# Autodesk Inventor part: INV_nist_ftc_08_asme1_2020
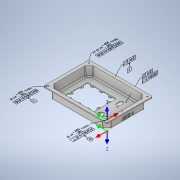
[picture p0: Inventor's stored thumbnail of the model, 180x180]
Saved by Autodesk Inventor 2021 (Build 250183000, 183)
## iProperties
Created: 2016-11
Part Number: INV_nist_ftc_08_asme1_2020
Material: Generic
Document SubType Name: Modeling
Designer: t_liuje
Density: 1 g/cm^3
Appearance: Default
Author: t_liuje
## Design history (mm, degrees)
node "Parallel Axes Pattern 1"
  node "Simple Hole 35"
  node "Simple Hole 36"
  node "Hole Note 13" dims "d5" = 291.1602, "d6" = 204.0382, "d141" = 22.86, "d142" = 22.86 (derived), "d143" = 22.86 (derived), "d144" = 22.86 (derived), "d145" = 22.86 (derived), "d146" = 22.86 (derived), "d147" = 22.86 (derived), "d148" = 22.86 (derived)
  node "Feature Control Frame 72"
node "Parallel Axes Pattern 2"
  node "Simple Hole 25"
  node "Simple Hole 26"
  node "Simple Hole 27"
  node "Simple Hole 28"
  node "Simple Hole 29"
  node "Simple Hole 30"
  node "Simple Hole 31"
  node "Simple Hole 32"
  node "Diameter Dimension 19" dims "d5" = 291.1602, "d6" = 204.0382, "d141" = 22.86, "d142" = 22.86 (derived), "d143" = 22.86 (derived), "d144" = 22.86 (derived), "d145" = 22.86 (derived), "d146" = 22.86 (derived), "d147" = 22.86 (derived), "d148" = 22.86 (derived), "d688" = 5.4102 (derived)
  node "Feature Control Frame 56"
node "Parallel Axes Pattern 3" dims "d231" = 9.14552 (derived), "d232" = 7.51656 (derived), "d233" = 0.508 (derived), "d234" = 0 (derived), "d235" = 0 (derived), "d236" = 1.524 (derived), "d237" = 0 (derived), "d238" = 0 (derived), "d247" = 27.94 (derived), "d315" = 5.33671 (derived), "d316" = 3.69003 (derived), "d347" = 15.24 (derived), "d348" = 0 (derived), "d349" = 0 (derived), "d505" = 0 (derived), "d506" = 0 (derived), "d541" = 3.50258 (derived), "d542" = 1.1618 (derived), "d543" = 1.524 (derived), "d544" = 0 (derived), "d545" = 0 (derived), "d598" = 0.2885 (derived), "d599" = 8.19502 (derived), "d600" = 0.381 (derived)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
  node "Simple Hole 33"
  node "Simple Hole 34"
  node "Diameter Dimension 20" dims "d5" = 291.1602, "d6" = 204.0382, "d141" = 22.86, "d142" = 22.86 (derived), "d143" = 22.86 (derived), "d144" = 22.86 (derived), "d145" = 22.86 (derived), "d146" = 22.86 (derived), "d147" = 22.86 (derived), "d148" = 22.86 (derived), "d717" = 6.35 (derived)
  node "Feature Control Frame 59"
  node "Datum Identifier 33" dims "d6" = 204.0382, "d231" = 9.14552 (derived), "d232" = 7.51656 (derived), "d233" = 0.508 (derived), "d234" = 0 (derived), "d235" = 0 (derived), "d236" = 1.524 (derived), "d237" = 0 (derived), "d238" = 0 (derived), "d247" = 27.94 (derived), "d315" = 5.33671 (derived), "d316" = 3.69003 (derived), "d347" = 15.24 (derived), "d348" = 0 (derived), "d349" = 0 (derived), "d505" = 0 (derived), "d506" = 0 (derived), "d541" = 3.50258 (derived), "d542" = 1.1618 (derived), "d543" = 1.524 (derived), "d544" = 0 (derived), "d545" = 0 (derived), "d598" = 0.2885 (derived), "d599" = 8.19502 (derived)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
node "Datum Reference Frame 16"
node "Datum Reference Frame 17"
node "Datum Reference Frame 18"
node "Datum Reference Frame 19"
node "Planar Surface 34"
  node "Feature Control Frame 43"
node "Planar Surface 35"
  node "Feature Control Frame 53"
  node "Leader Text 16"
node "Extruded Group 5"
  node "Cylindrical Surface 19"
  node "Planar Surface 40"
  node "Planar Surface 41"
  node "Planar Surface 42"
  node "Planar Surface 43"
  node "Planar Surface 44"
  node "Cylindrical Surface 20"
  node "Cylindrical Surface 21"
  node "Planar Surface 45"
  node "Planar Surface 46"
  node "Feature Control Frame 67"
node "Extruded Group 6"
  node "Planar Surface 47"
  node "Cylindrical Surface 24"
  node "Cylindrical Surface 25"
  node "Cylindrical Surface 26"
  node "Planar Surface 48"
  node "Cylindrical Surface 27"
  node "Planar Surface 49"
  node "Cylindrical Surface 28"
  node "Cylindrical Surface 29"
  node "Cylindrical Surface 30"
  node "Planar Surface 50"
  node "Cylindrical Surface 31"
  node "Cylindrical Surface 32"
  node "Cylindrical Surface 33"
  node "Planar Surface 51"
  node "Cylindrical Surface 34"
  node "Planar Surface 52"
  node "Cylindrical Surface 35"
  node "Cylindrical Surface 36"
  node "Cylindrical Surface 37"
  node "Planar Surface 53"
  node "Cylindrical Surface 38"
  node "Cylindrical Surface 39"
  node "Cylindrical Surface 40"
  node "Planar Surface 54"
  node "Cylindrical Surface 41"
  node "Cylindrical Surface 42"
  node "Cylindrical Surface 43"
  node "Planar Surface 55"
  node "Cylindrical Surface 44"
  node "Planar Surface 56"
  node "Cylindrical Surface 45"
  node "Cylindrical Surface 46"
  node "Cylindrical Surface 47"
  node "Planar Surface 57"
  node "Cylindrical Surface 48"
  node "Cylindrical Surface 49"
  node "Cylindrical Surface 50"
  node "Planar Surface 58"
  node "Cylindrical Surface 51"
  node "Planar Surface 59"
  node "Cylindrical Surface 52"
  node "Cylindrical Surface 53"
  node "Cylindrical Surface 54"
  node "Planar Surface 60"
  node "Cylindrical Surface 55"
  node "Cylindrical Surface 56"
  node "Cylindrical Surface 57"
  node "Feature Control Frame 73"
node "Extruded Group 7"
  node "Planar Surface 61"
  node "Cylindrical Surface 58"
  node "Planar Surface 62"
  node "Cylindrical Surface 59"
  node "Planar Surface 63"
  node "Planar Surface 64"
  node "Cylindrical Surface 60"
  node "Cylindrical Surface 61"
  node "Feature Control Frame 74"
body "Solid1"
node "Blocks"
node "Annotations"
node "Tolerance Features"
sketch "Sketch1"
  geometry: L1 (155.804, -111.354)-(-155.804, -111.354); L2 (-155.804, -111.354)-(-155.804, 111.354); L3 (-155.804, 111.354)-(155.804, 111.354); L4 (155.804, 111.354)-(155.804, -111.354); L5 (0, -145.063)-(0, 157.515); L6 (136.916, 0)-(-164.263, 0); 1 further point
  constraints: 12 end point, 2 horizontal, 2 parallel, 2 point on line, 1 perpendicular, 1 vertical, 2 other
  dimensions: "d0" = 311.6072 distance of L2.end L3.end; "d1" = 222.7072 distance of L1.end L2.end
extrude "Extrusion1" new body sketch "Sketch1" distance "d2" = 10.16; taper "d3" = 0 deg
feature "FaceDraft1" dims angle "d4" = -2.5 deg
sketch "Sketch2"
  geometry: L1 (0, -151.447)-(0, 170.59); L2 (373.907, 0)-(-297.418, 0); L3 (-122.72, -102.019)-(122.72, -102.019); L4 (145.58, -79.159)-(145.58, 79.159); L5 (122.72, 102.019)-(-122.72, 102.019); L6 (-145.58, 79.159)-(-145.58, -79.159); L7 (-122.72, 102.019)-(-145.58, 79.159); L8 (-145.58, -79.159)-(-122.72, -102.019); L9 (122.72, -102.019)-(145.58, -79.159); L10 (145.58, 79.159)-(122.72, 102.019); 5 further points
  constraints: 20 end point, 10 point on line, 2 horizontal, 2 parallel, 1 perpendicular, 1 vertical, 2 other
  dimensions: "d5" = 291.1602 distance of point (145.58, 102.019) point (-145.58, 102.019); "d6" = 204.0382 distance of point (145.58, -102.019) point (145.58, 102.019); "d141" = 22.86 distance of L5.end point (-145.58, 102.019); "d142" = 22.86 distance of L6.start point (-145.58, 102.019) (derived); "d143" = 22.86 distance of L6.end point (-145.58, -102.019) (derived); "d144" = 22.86 distance of L3.start point (-145.58, -102.019) (derived); "d145" = 22.86 distance of L3.end point (145.58, -102.019) (derived); "d146" = 22.86 distance of L4.start point (145.58, -102.019) (derived); "d147" = 22.86 distance of L4.end point (145.58, 102.019) (derived); "d148" = 22.86 distance of L5.start point (145.58, 102.019) (derived)
extrude "Extrusion2" join sketch "Sketch2" distance "d7" = 38.1; taper "d8" = 0 deg
feature "FaceDraft2" dims angle "d9" = 2.5 deg
workplane "Work Plane1"
sketch "Sketch3"
  geometry: L1 (0, -206.645)-(0, 206.645); L2 (-285.873, 0)-(333.246, 0); L3 (-119.456, -94.158)-(119.456, -94.158); L4 (137.719, -75.895)-(137.719, 75.895); L5 (119.456, 94.158)-(-119.456, 94.158); L6 (-137.719, 75.895)-(-137.719, -75.895); L7 (-119.456, -94.158)-(-137.719, -75.895); L8 (-137.719, 75.895)-(-119.456, 94.158); L9 (119.456, 94.158)-(137.719, 75.895); L10 (119.456, -94.158)-(137.719, -75.895); 6 further points
  constraints: 20 end point, 9 point on line, 2 parallel, 2 perpendicular, 1 coincident, 1 horizontal, 1 midpoint, 1 vertical, 2 other
  dimensions: "d11" = 275.4376 distance of point (-137.719, 94.158) point (137.719, 94.158); "d12" = 188.3156 distance of point (137.719, 94.158) point (137.719, -94.158); "d16" = 18.2626 distance of L3.start point (-137.719, -94.158); "d17" = 18.2626 distance of L6.end point (-137.719, -94.158) (= d16); "d18" = 18.2626 distance of L6.start point (-137.719, 94.158) (= d16); "d19" = 18.2626 distance of L5.end point (-137.719, 94.158) (= d18); "d20" = 18.2626 distance of L5.start point (137.719, 94.158) (= d16); "d21" = 18.2626 distance of L4.end point (137.719, 94.158) (= d20); "d22" = 18.2626 distance of L3.end point (137.719, -94.158) (= d16); "d23" = 18.2626 distance of L4.start point (137.719, -94.158) (= d22)
extrude "Extrusion3" cut sketch "Sketch3" stored distance "d13" = 38.1; taper "d14" = 0 deg
feature "FaceDraft3" dims angle "d15" = 2.5 deg
fillet "Fillet1" dims "d24" = 3.048
fillet "Fillet2" dims "d25" = 6.096
sketch "Sketch4"
  geometry: L1 (-127.635, 79.375)-(-121.285, 79.375); L2 (-118.11, 76.2)-(-118.11, -76.2); L3 (-121.285, -79.375)-(-127.635, -79.375); L4 (-130.81, -76.2)-(-130.81, 76.2); L5 (-237.716, 0)-(182.507, 0); L6 (-155.804, -105.263)-(-155.804, 105.263) reference; A1 r 3.175 centre (-127.635, 76.2) between (-127.635, 79.375) and (-130.81, 76.2); A2 r 3.175 centre (-121.285, 76.2) between (-118.11, 76.2) and (-121.285, 79.375); A3 r 3.175 centre (-127.635, -76.2) between (-130.81, -76.2) and (-127.635, -79.375); A4 r 3.175 centre (-121.285, -76.2) between (-121.285, -79.375) and (-118.11, -76.2); 4 further points
  constraints: 10 end point, 8 point on circle, 8 tangent, 7 point on line, 4 centre point, 3 equal radius, 2 horizontal, 2 parallel, 1 perpendicular, 1 other
  dimensions: "d26" = 12.7 distance of point (-118.11, -79.375) point (-130.81, -79.375); "d27" = 158.75 distance of point (-118.11, 79.375) point (-118.11, -79.375); "d28" = 24.9936 distance between parallel lines of L6 L4; "d29" = 3.175 radius of A1
extrude "Extrusion4" cut sketch "Sketch4" distance "d30" = 1.27; taper "d31" = 0 deg
fillet "Fillet3" dims "d32" = 0.762
sketch "Sketch5"
  geometry: L1 (-252.407, 0)-(214.454, 0); L2 (0, 149.282)-(0, -167.26); L3 (-155.804, -105.263)-(-155.804, 105.263) reference; L4 (-90.016, -57.15)-(-107.95, -57.15); L5 (-45.566, -57.15)-(-75.084, -57.15); L6 (31.75, -57.15)-(13.816, -57.15); L7 (0, -57.15)-(-30.634, -57.15); L8 (31.75, -32.866)-(31.75, -57.15); L9 (31.75, 57.15)-(31.75, 32.866); L10 (31.75, 17.934)-(31.75, -17.934); L11 (13.816, 57.15)-(31.75, 57.15); L12 (-30.634, 57.15)-(0, 57.15); L13 (-107.95, 57.15)-(-90.016, 57.15); L14 (-75.084, 57.15)-(-45.566, 57.15); L15 (-107.95, 32.866)-(-107.95, 57.15); L16 (-107.95, -57.15)-(-107.95, -32.866); L17 (-107.95, -17.934)-(-107.95, 17.934); L18 (155.804, 105.263)-(155.804, -105.263) reference; L19 (-149.713, 111.354)-(149.713, 111.354) reference; L20 (46.99, 52.705)-(52.07, 52.705); L21 (52.07, 40.005)-(46.99, 40.005); L22 (46.99, 40.005)-(46.99, 52.705); L23 (52.07, 38.1)-(52.07, 40.005); L24 (52.07, 52.705)-(52.07, 54.61); L25 (67.31, 54.61)-(67.31, 51.435); L26 (67.31, 41.275)-(67.31, 38.1); L27 (96.85, -35.56)-(121.59, -35.56); L28 (123.19, -37.16)-(123.19, -61.9); L29 (121.59, -63.5)-(96.85, -63.5); L30 (95.25, -61.9)-(95.25, -37.16); L31 (149.713, -111.354)-(-149.713, -111.354) reference; L32 (67.31, -38.1)-(67.31, -41.275); L33 (67.31, -51.435)-(67.31, -54.61); L34 (52.07, -38.1)-(52.07, -54.61); C1 r 2.705 at (-82.55, 55.626); C2 r 2.705 at (-38.1, 55.626); C3 r 2.705 at (6.35, 55.626); C4 r 2.705 at (-82.55, -55.626); C5 r 2.705 at (-38.1, -55.626); C6 r 2.705 at (6.35, -55.626); C7 r 2.705 at (-106.426, 25.4); C8 r 2.705 at (-106.426, -25.4); C9 r 2.705 at (30.226, 25.4); C10 r 2.705 at (30.226, -25.4); C11 r 3.073 at (69.85, 67.31); C12 r 2.896 at (69.85, 25.4); C13 r 3.175 at (109.22, -20.955); C14 r 3.175 at (109.22, -78.105); C15 r 2.896 at (69.85, -67.31); C16 r 3.073 at (69.85, -25.4); A1 r 7.62 centre (-82.55, 55.626) between (-90.016, 57.15) and (-75.084, 57.15); A2 r 7.62 centre (-38.1, 55.626) between (-45.566, 57.15) and (-30.634, 57.15); A3 r 7.62 centre (6.35, 55.626) between (-1.116, 57.15) and (13.816, 57.15); A4 r 7.62 centre (-82.55, -55.626) between (-75.084, -57.15) and (-90.016, -57.15); A5 r 7.62 centre (-38.1, -55.626) between (-30.634, -57.15) and (-45.566, -57.15); A6 r 7.62 centre (6.35, -55.626) between (13.816, -57.15) and (-1.116, -57.15); A7 r 7.62 centre (-106.426, 25.4) between (-107.95, 17.934) and (-107.95, 32.866); A8 r 7.62 centre (-106.426, -25.4) between (-107.95, -32.866) and (-107.95, -17.934); A9 r 7.62 centre (30.226, 25.4) between (31.75, 32.866) and (31.75, 17.934); A10 r 7.62 centre (30.226, -25.4) between (31.75, -17.934) and (31.75, -32.866); A11 r 15.291 centre (111.76, 63.5) between (96.787, 60.397) and (96.787, 66.603); A12 r 3.175 centre (97.46, 63.5) between (96.787, 66.603) and (96.787, 60.397); A13 r 5.08 centre (67.31, 46.355) between (67.31, 41.275) and (67.31, 51.435); A14 r 7.62 centre (59.69, 54.61) between (67.31, 54.61) and (52.07, 54.61); A15 r 7.62 centre (59.69, 38.1) between (52.07, 38.1) and (67.31, 38.1); A16 r 1.6 centre (96.85, -37.16) between (96.85, -35.56) and (95.25, -37.16); A17 r 1.6 centre (121.59, -37.16) between (123.19, -37.16) and (121.59, -35.56); A18 r 1.6 centre (96.85, -61.9) between (95.25, -61.9) and (96.85, -63.5); A19 r 1.6 centre (121.59, -61.9) between (121.59, -63.5) and (123.19, -61.9); A20 r 7.62 centre (59.69, -54.61) between (52.07, -54.61) and (67.31, -54.61); A21 r 7.62 centre (59.69, -38.1) between (67.31, -38.1) and (52.07, -38.1); A22 r 5.08 centre (67.31, -46.355) between (67.31, -51.435) and (67.31, -41.275); 4 further points
  constraints: 60 end point, 44 point on circle, 38 centre point, 32 parallel, 16 point on line, 16 tangent, 13 perpendicular, 10 coincident, 10 collinear, 7 horizontal, 4 equal radius, 4 vertical, 2 symmetric about line, 1 other
  dimensions: "d33" = 139.7 distance of L6.start L4.end; "d34" = 114.3 distance of L9.start L6.start; "d36" = 5.4102 diameter of C1; "d39" = 15.24 diameter of A1; "d40" = 5.4102 diameter of C2; "d41" = 15.24 diameter of A2; "d42" = 5.4102 diameter of C3; "d43" = 15.24 diameter of A3; "d48" = 44.45 distance of A2.centre A1.centre; "d49" = 44.45 distance of A2.centre A3.centre; "d50" = 5.4102 diameter of C4; "d51" = 15.24 diameter of A4; "d52" = 5.4102 diameter of C5; "d53" = 15.24 diameter of A5; "d54" = 5.4102 diameter of C6; "d55" = 15.24 diameter of A6; "d56" = 44.45 distance of A5.centre A4.centre; "d57" = 44.45 distance of A5.centre A6.centre; "d62" = 44.45 distance of C4.centre C5.centre (derived); "d63" = 44.45 distance of C6.centre C5.centre (derived); "d64" = 5.4102 diameter of C7; "d65" = 15.24 diameter of A7; "d66" = 5.4102 diameter of C8; "d67" = 15.24 diameter of A8; "d68" = 50.8 distance of A8.centre C7.centre; "d70" = 5.4102 diameter of C9; "d71" = 15.24 diameter of A9; "d72" = 5.4102 diameter of C10; "d73" = 15.24 diameter of A10; "d74" = 50.8 distance of A10.centre C9.centre; "d76" = 114.3 distance between parallel lines of L5 L14; "d77" = 139.7 distance between parallel lines of L10 L17; "d78" = 47.8536 distance between parallel lines of L3 L17; "d79" = 1.524 distance from line of L14 C1.centre; "d80" = 25.4 distance from line of L15 C1.centre; "d81" = 1.524 distance from line of L12 A2.centre; "d82" = 1.524 distance from line of L12 A3.centre; "d83" = 1.524 distance from line of L5 C4.centre; "d84" = 1.524 distance from line of A5.centre L5; "d85" = 25.4 distance from line of L16 A4.centre; "d86" = 1.524 distance from line of L6 A6.centre; "d87" = 1.524 distance from line of L8 A10.centre; "d88" = 1.524 distance from line of L16 C8.centre; "d89" = 30.5816 diameter of A11; "d90" = 44.0436 distance from line of L18 A11.centre; "d91" = 47.8536 distance from line of A11.centre L19; "d92" = 14.3002 distance of A12.centre A11.centre; "d93" = 47.8536 distance from line of A12.centre L19 (= d91); "d94" = 6.35 diameter of A12; "d95" = 10.16 diameter of A13; "d96" = 5.08 distance between parallel lines of L24 L22; "d97" = 5.08 distance of L21.start L21.end (= d96); "d98" = 12.7 distance of L21.end L20.start; "d99" = 15.24 distance between parallel lines of L24 L25; "d100" = 6.35 distance from line of A13.centre L20; "d101" = 56.7436 distance from line of L19 A14.centre; "d102" = 96.1136 distance from line of L18 A14.centre; "d103" = 16.51 distance of A15.centre A14.centre; "d104" = 1.905 distance from line of A14.centre L20; "d105" = 6.1468 diameter of C11; "d106" = 10.16 horizontal distance of C11.centre A14.centre; "d107" = 12.7 vertical distance of A14.centre C11.centre; "d108" = 10.16 horizontal distance of A15.centre C12.centre (derived); "d109" = 12.7 vertical distance of A15.centre C12.centre (derived)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
extrude "Extrusion5" cut sketch "Sketch5" stored distance "d130" = 25.4; taper "d131" = 0 deg
sketch "Sketch8"
  geometry: L1 (149.713, 111.354)-(-149.713, 111.354) reference; L2 (-155.804, 105.263)-(-155.804, -105.263) reference; 1 further point
  dimensions: "d132" = 12.9286 distance from line of L1 point (-142.875, 98.425); "d133" = 12.9286 distance from line of L2 point (-142.875, 98.425)
hole "Hole1" sketch "Sketch8" diameter "d134" = 6.0452; stored, may be unused: countersink angle "d138" = 82 deg, drill point angle "d140" = 118 deg; dims "d135" = 19.05, "d136" = 9.525, "d137" = 6.35, "d139" = 12.7
mirror "Mirror1"
mirror "Mirror2"
sketch "Sketch6"
  geometry: L1 (183.284, 13.514)-(183.095, 9.18) reference; L2 (183.095, 9.18)-(189.186, 8.914) reference; L3 (189.186, 8.914)-(189.375, 13.248) reference; L4 (-27.242, 13.514)-(183.284, 13.514) reference; 2 further points; 1 other entity
  constraints: 1 other
  dimensions: "d150" = 83.4136 dimension on L3.end; "d151" = 25.4 dimension on L4
extrude "Extrusion6" cut sketch "Sketch6" distance "d152" = 2.54; taper "d153" = 0 deg
fillet "Fillet4" dims "d196" = 3.175
sketch "Sketch7"
  geometry: L1 (70.782, -29.383)-(70.782, 0); L2 (170.85, 0)-(170.85, -29.383); L3 (170.85, -29.383)-(141.467, 0); L4 (160.074, -29.383)-(130.691, 0); L5 (149.297, -29.383)-(119.915, 0); L6 (138.521, -29.383)-(109.138, 0); L7 (127.745, -29.383)-(98.362, 0); L8 (116.969, -29.383)-(87.586, 0); L9 (106.192, -29.383)-(76.809, 0); L10 (95.416, -29.383)-(70.782, -4.749); L11 (84.64, -29.383)-(70.782, -15.525); L12 (73.863, -29.383)-(70.782, -26.301); L13 (170.85, -18.607)-(152.244, 0); L14 (170.85, -7.83)-(163.02, 0)
  constraints: 28 end point, 12 parallel, 5 point on line, 1 vertical, 24 other
split "Split1"
sketch "Block1"
  geometry: L1 (17.204, 76.896)-(6.4, 76.896); L2 (18.296, 92.7)-(18.296, 77.988); L3 (15.48, 83.59)-(15.48, 92.642); L4 (6.4, 108.85)-(6.4, 83.246); L5 (9.561, 108.85)-(6.4, 108.85); L6 (9.561, 102.44)-(9.561, 108.85); L7 (21.4, 102.44)-(9.561, 102.44); L8 (21.4, 99.338)-(21.4, 102.44); L9 (9.561, 99.338)-(21.4, 99.338); L10 (9.561, 83.648)-(9.561, 99.338); L11 (12.377, 93.16)-(12.377, 83.533); L12 (21.4, 77.959)-(21.4, 93.16); L13 (6.4, 73.763)-(17.204, 73.763); L14 (6.4, 76.896)-(6.4, 73.763); L15 (18.124, 67.902)-(7.023, 57.637); L16 (6.4, 68.62)-(17.808, 68.62); L17 (6.4, 71.752)-(6.4, 68.62); L18 (17.882, 71.752)-(6.4, 71.752); L19 (9.79, 56.022)-(20.08, 65.489); L20 (21.4, 55.085)-(10.156, 55.085); L21 (21.4, 51.982)-(21.4, 55.085); L22 (9.237, 51.982)-(21.4, 51.982); A1 r 1.093 centre (17.204, 77.988) between (17.204, 76.896) and (18.296, 77.988); A2 r 1.417 centre (16.891, 92.519) between (18.296, 92.7) and (15.48, 92.642); A3 r 4.547 centre (10.946, 83.246) between (6.4, 83.246) and (15.48, 83.59); A4 r 1.41 centre (10.966, 83.533) between (9.561, 83.648) and (12.377, 83.533); A5 r 4.568 centre (16.888, 92.441) between (21.4, 93.16) and (12.377, 93.16); A6 r 4.196 centre (17.204, 77.959) between (17.204, 73.763) and (21.4, 77.959); A7 r 3.261 centre (9.237, 55.243) between (7.023, 57.637) and (9.237, 51.982); A8 r 0.415 centre (17.842, 68.207) between (18.124, 67.902) and (17.808, 68.62); A9 r 3.517 centre (17.882, 68.235) between (20.08, 65.489) and (17.882, 71.752); A10 r 0.54 centre (10.156, 55.625) between (9.79, 56.022) and (10.156, 55.085); 1 further point
  constraints: 44 end point, 20 point on circle, 10 centre point
node "Projected Loop1"
node "Block1:1" dims "d150" = 83.4136, "d151" = 25.4
node "Planar Surface 1" dims "d231" = 9.14552 (derived), "d232" = 7.51656 (derived), "d233" = 0.508 (derived), "d234" = 0 (derived), "d235" = 0 (derived), "d236" = 1.524 (derived), "d237" = 0 (derived), "d238" = 0 (derived), "d247" = 27.94 (derived), "d315" = 5.33671 (derived), "d316" = 3.69003 (derived), "d347" = 15.24 (derived), "d348" = 0 (derived), "d349" = 0 (derived), "d505" = 0 (derived), "d506" = 0 (derived), "d541" = 3.50258 (derived), "d542" = 1.1618 (derived), "d543" = 1.524 (derived), "d544" = 0 (derived), "d545" = 0 (derived), "d598" = 0.2885 (derived), "d599" = 8.19502 (derived), "d600" = 0.381 (derived)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
node "Datum Reference Frame 1"
node "Simple Hole 1" dims "d231" = 9.14552 (derived), "d232" = 7.51656 (derived), "d233" = 0.508 (derived), "d234" = 0 (derived), "d235" = 0 (derived), "d236" = 1.524 (derived), "d237" = 0 (derived), "d238" = 0 (derived), "d247" = 27.94 (derived), "d315" = 5.33671 (derived), "d316" = 3.69003 (derived), "d347" = 15.24 (derived), "d348" = 0 (derived), "d349" = 0 (derived), "d505" = 0 (derived), "d506" = 0 (derived), "d541" = 3.50258 (derived), "d542" = 1.1618 (derived), "d543" = 1.524 (derived), "d544" = 0 (derived), "d545" = 0 (derived), "d598" = 0.2885 (derived), "d599" = 8.19502 (derived), "d600" = 0.381 (derived)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
node "Datum Reference Frame 2"
node "Simple Hole 2" dims "d231" = 9.14552 (derived), "d232" = 7.51656 (derived), "d233" = 0.508 (derived), "d234" = 0 (derived), "d235" = 0 (derived), "d236" = 1.524 (derived), "d237" = 0 (derived), "d238" = 0 (derived), "d247" = 27.94 (derived), "d315" = 5.33671 (derived), "d316" = 3.69003 (derived), "d347" = 15.24 (derived), "d348" = 0 (derived), "d349" = 0 (derived), "d505" = 0 (derived), "d506" = 0 (derived), "d541" = 3.50258 (derived), "d542" = 1.1618 (derived), "d543" = 1.524 (derived), "d544" = 0 (derived), "d545" = 0 (derived), "d598" = 0.2885 (derived), "d599" = 8.19502 (derived), "d600" = 0.381 (derived)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
node "Datum Reference Frame 3"
node "Datum Reference Frame 4"
node "Datum Reference Frame 5"
node "Planar Surface 2" dims "d231" = 9.14552 (derived), "d232" = 7.51656 (derived), "d233" = 0.508 (derived), "d234" = 0 (derived), "d235" = 0 (derived), "d236" = 1.524 (derived), "d237" = 0 (derived), "d238" = 0 (derived), "d247" = 27.94 (derived), "d315" = 5.33671 (derived), "d316" = 3.69003 (derived), "d347" = 15.24 (derived), "d348" = 0 (derived), "d349" = 0 (derived), "d505" = 0 (derived), "d506" = 0 (derived), "d541" = 3.50258 (derived), "d542" = 1.1618 (derived), "d543" = 1.524 (derived), "d544" = 0 (derived), "d545" = 0 (derived), "d598" = 0.2885 (derived), "d599" = 8.19502 (derived), "d600" = 0.381 (derived)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
node "Datum Reference Frame 6"
node "Simple Hole 5" dims "d231" = 9.14552 (derived), "d232" = 7.51656 (derived), "d233" = 0.508 (derived), "d234" = 0 (derived), "d235" = 0 (derived), "d236" = 1.524 (derived), "d237" = 0 (derived), "d238" = 0 (derived), "d247" = 27.94 (derived), "d315" = 5.33671 (derived), "d316" = 3.69003 (derived), "d347" = 15.24 (derived), "d348" = 0 (derived), "d349" = 0 (derived), "d505" = 0 (derived), "d506" = 0 (derived), "d541" = 3.50258 (derived), "d542" = 1.1618 (derived), "d543" = 1.524 (derived), "d544" = 0 (derived), "d545" = 0 (derived), "d598" = 0.2885 (derived), "d599" = 8.19502 (derived), "d600" = 0.381 (derived)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
node "Datum Reference Frame 7"
node "Simple Hole 6" dims "d231" = 9.14552 (derived), "d232" = 7.51656 (derived), "d233" = 0.508 (derived), "d234" = 0 (derived), "d235" = 0 (derived), "d236" = 1.524 (derived), "d237" = 0 (derived), "d238" = 0 (derived), "d247" = 27.94 (derived), "d315" = 5.33671 (derived), "d316" = 3.69003 (derived), "d347" = 15.24 (derived), "d348" = 0 (derived), "d349" = 0 (derived), "d505" = 0 (derived), "d506" = 0 (derived), "d541" = 3.50258 (derived), "d542" = 1.1618 (derived), "d543" = 1.524 (derived), "d544" = 0 (derived), "d545" = 0 (derived), "d598" = 0.2885 (derived), "d599" = 8.19502 (derived), "d600" = 0.381 (derived)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
node "Datum Reference Frame 8"
node "Datum Reference Frame 9"
node "Planar Surface 3"
node "Planar Surface 4"
node "Datum Reference Frame 10"
node "Planar Surface 7"
node "Feature Control Frame 11"
node "Extruded Group 1"
node "Linear Dimension 1" dims "d5" = 291.1602, "d6" = 204.0382, "d141" = 22.86, "d142" = 22.86 (derived), "d143" = 22.86 (derived), "d144" = 22.86 (derived), "d145" = 22.86 (derived), "d146" = 22.86 (derived), "d147" = 22.86 (derived), "d148" = 22.86 (derived), "d247" = 27.94 (derived)
node "Datum Reference Frame 11"
node "Simple Hole 17" dims "d231" = 9.14552 (derived), "d232" = 7.51656 (derived), "d233" = 0.508 (derived), "d234" = 0 (derived), "d235" = 0 (derived), "d236" = 1.524 (derived), "d237" = 0 (derived), "d238" = 0 (derived), "d247" = 27.94 (derived), "d315" = 5.33671 (derived), "d316" = 3.69003 (derived), "d347" = 15.24 (derived), "d348" = 0 (derived), "d349" = 0 (derived), "d505" = 0 (derived), "d506" = 0 (derived), "d541" = 3.50258 (derived), "d542" = 1.1618 (derived), "d543" = 1.524 (derived), "d544" = 0 (derived), "d545" = 0 (derived), "d598" = 0.2885 (derived), "d599" = 8.19502 (derived), "d600" = 0.381 (derived)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
node "Datum Reference Frame 12"
node "Simple Hole 18" dims "d231" = 9.14552 (derived), "d232" = 7.51656 (derived), "d233" = 0.508 (derived), "d234" = 0 (derived), "d235" = 0 (derived), "d236" = 1.524 (derived), "d237" = 0 (derived), "d238" = 0 (derived), "d247" = 27.94 (derived), "d315" = 5.33671 (derived), "d316" = 3.69003 (derived), "d347" = 15.24 (derived), "d348" = 0 (derived), "d349" = 0 (derived), "d505" = 0 (derived), "d506" = 0 (derived), "d541" = 3.50258 (derived), "d542" = 1.1618 (derived), "d543" = 1.524 (derived), "d544" = 0 (derived), "d545" = 0 (derived), "d598" = 0.2885 (derived), "d599" = 8.19502 (derived), "d600" = 0.381 (derived)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
node "Datum Reference Frame 13"
node "Simple Hole 19" dims "d231" = 9.14552 (derived), "d232" = 7.51656 (derived), "d233" = 0.508 (derived), "d234" = 0 (derived), "d235" = 0 (derived), "d236" = 1.524 (derived), "d237" = 0 (derived), "d238" = 0 (derived), "d247" = 27.94 (derived), "d315" = 5.33671 (derived), "d316" = 3.69003 (derived), "d347" = 15.24 (derived), "d348" = 0 (derived), "d349" = 0 (derived), "d505" = 0 (derived), "d506" = 0 (derived), "d541" = 3.50258 (derived), "d542" = 1.1618 (derived), "d543" = 1.524 (derived), "d544" = 0 (derived), "d545" = 0 (derived), "d598" = 0.2885 (derived), "d599" = 8.19502 (derived), "d600" = 0.381 (derived)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
node "Datum Reference Frame 14"
node "Simple Hole 20" dims "d231" = 9.14552 (derived), "d232" = 7.51656 (derived), "d233" = 0.508 (derived), "d234" = 0 (derived), "d235" = 0 (derived), "d236" = 1.524 (derived), "d237" = 0 (derived), "d238" = 0 (derived), "d247" = 27.94 (derived), "d315" = 5.33671 (derived), "d316" = 3.69003 (derived), "d347" = 15.24 (derived), "d348" = 0 (derived), "d349" = 0 (derived), "d505" = 0 (derived), "d506" = 0 (derived), "d541" = 3.50258 (derived), "d542" = 1.1618 (derived), "d543" = 1.524 (derived), "d544" = 0 (derived), "d545" = 0 (derived), "d598" = 0.2885 (derived), "d599" = 8.19502 (derived), "d600" = 0.381 (derived)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
node "Datum Reference Frame 15"
node "General Note 1"
node "Leader Text 5"
node "Leader Text 6"
node "General Surface Profile Tolerance"
node "Hole Note 1" dims "d5" = 291.1602, "d6" = 204.0382, "d141" = 22.86, "d142" = 22.86 (derived), "d143" = 22.86 (derived), "d144" = 22.86 (derived), "d145" = 22.86 (derived), "d146" = 22.86 (derived), "d147" = 22.86 (derived), "d148" = 22.86 (derived)
node "Feature Control Frame 54"
node "Datum Identifier 31" dims "d6" = 204.0382, "d231" = 9.14552 (derived), "d232" = 7.51656 (derived), "d233" = 0.508 (derived), "d234" = 0 (derived), "d235" = 0 (derived), "d236" = 1.524 (derived), "d237" = 0 (derived), "d238" = 0 (derived), "d247" = 27.94 (derived), "d315" = 5.33671 (derived), "d316" = 3.69003 (derived), "d347" = 15.24 (derived), "d348" = 0 (derived), "d349" = 0 (derived), "d505" = 0 (derived), "d506" = 0 (derived), "d541" = 3.50258 (derived), "d542" = 1.1618 (derived), "d543" = 1.524 (derived), "d544" = 0 (derived), "d545" = 0 (derived), "d598" = 0.2885 (derived), "d599" = 8.19502 (derived)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
node "Feature Control Frame 55" dims "d231" = 9.14552 (derived), "d232" = 7.51656 (derived), "d233" = 0.508 (derived), "d234" = 0 (derived), "d235" = 0 (derived), "d236" = 1.524 (derived), "d237" = 0 (derived), "d238" = 0 (derived), "d247" = 27.94 (derived), "d315" = 5.33671 (derived), "d316" = 3.69003 (derived), "d347" = 15.24 (derived), "d348" = 0 (derived), "d349" = 0 (derived), "d505" = 0 (derived), "d506" = 0 (derived), "d541" = 3.50258 (derived), "d542" = 1.1618 (derived), "d543" = 1.524 (derived), "d544" = 0 (derived), "d545" = 0 (derived), "d598" = 0.2885 (derived), "d599" = 8.19502 (derived), "d600" = 0.381 (derived)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
node "Feature Control Frame 57"
node "Datum Identifier 32" dims "d6" = 204.0382, "d231" = 9.14552 (derived), "d232" = 7.51656 (derived), "d233" = 0.508 (derived), "d234" = 0 (derived), "d235" = 0 (derived), "d236" = 1.524 (derived), "d237" = 0 (derived), "d238" = 0 (derived), "d247" = 27.94 (derived), "d315" = 5.33671 (derived), "d316" = 3.69003 (derived), "d347" = 15.24 (derived), "d348" = 0 (derived), "d349" = 0 (derived), "d505" = 0 (derived), "d506" = 0 (derived), "d541" = 3.50258 (derived), "d542" = 1.1618 (derived), "d543" = 1.524 (derived), "d544" = 0 (derived), "d545" = 0 (derived), "d598" = 0.2885 (derived), "d599" = 8.19502 (derived)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
node "Feature Control Frame 58"
node "Diameter Dimension 7" dims "d5" = 291.1602, "d6" = 204.0382, "d141" = 22.86, "d142" = 22.86 (derived), "d143" = 22.86 (derived), "d144" = 22.86 (derived), "d145" = 22.86 (derived), "d146" = 22.86 (derived), "d147" = 22.86 (derived), "d148" = 22.86 (derived), "d759" = 5.7912 (derived)
node "Feature Control Frame 64"
node "Datum Identifier 38" dims "d6" = 204.0382, "d231" = 9.14552 (derived), "d232" = 7.51656 (derived), "d233" = 0.508 (derived), "d234" = 0 (derived), "d235" = 0 (derived), "d236" = 1.524 (derived), "d237" = 0 (derived), "d238" = 0 (derived), "d247" = 27.94 (derived), "d315" = 5.33671 (derived), "d316" = 3.69003 (derived), "d347" = 15.24 (derived), "d348" = 0 (derived), "d349" = 0 (derived), "d505" = 0 (derived), "d506" = 0 (derived), "d541" = 3.50258 (derived), "d542" = 1.1618 (derived), "d543" = 1.524 (derived), "d544" = 0 (derived), "d545" = 0 (derived), "d598" = 0.2885 (derived), "d599" = 8.19502 (derived)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
node "Leader Text 21"
node "Diameter Dimension 6" dims "d5" = 291.1602, "d6" = 204.0382, "d141" = 22.86, "d142" = 22.86 (derived), "d143" = 22.86 (derived), "d144" = 22.86 (derived), "d145" = 22.86 (derived), "d146" = 22.86 (derived), "d147" = 22.86 (derived), "d148" = 22.86 (derived), "d766" = 6.1468 (derived)
node "Feature Control Frame 65"
node "Datum Identifier 39" dims "d6" = 204.0382, "d231" = 9.14552 (derived), "d232" = 7.51656 (derived), "d233" = 0.508 (derived), "d234" = 0 (derived), "d235" = 0 (derived), "d236" = 1.524 (derived), "d237" = 0 (derived), "d238" = 0 (derived), "d247" = 27.94 (derived), "d315" = 5.33671 (derived), "d316" = 3.69003 (derived), "d347" = 15.24 (derived), "d348" = 0 (derived), "d349" = 0 (derived), "d505" = 0 (derived), "d506" = 0 (derived), "d541" = 3.50258 (derived), "d542" = 1.1618 (derived), "d543" = 1.524 (derived), "d544" = 0 (derived), "d545" = 0 (derived), "d598" = 0.2885 (derived), "d599" = 8.19502 (derived)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
node "Leader Text 22"
node "Diameter Dimension 5" dims "d5" = 291.1602, "d6" = 204.0382, "d141" = 22.86, "d142" = 22.86 (derived), "d143" = 22.86 (derived), "d144" = 22.86 (derived), "d145" = 22.86 (derived), "d146" = 22.86 (derived), "d147" = 22.86 (derived), "d148" = 22.86 (derived), "d773" = 5.7912 (derived)
node "Feature Control Frame 66"
node "Datum Identifier 40" dims "d6" = 204.0382, "d231" = 9.14552 (derived), "d232" = 7.51656 (derived), "d233" = 0.508 (derived), "d234" = 0 (derived), "d235" = 0 (derived), "d236" = 1.524 (derived), "d237" = 0 (derived), "d238" = 0 (derived), "d247" = 27.94 (derived), "d315" = 5.33671 (derived), "d316" = 3.69003 (derived), "d347" = 15.24 (derived), "d348" = 0 (derived), "d349" = 0 (derived), "d505" = 0 (derived), "d506" = 0 (derived), "d541" = 3.50258 (derived), "d542" = 1.1618 (derived), "d543" = 1.524 (derived), "d544" = 0 (derived), "d545" = 0 (derived), "d598" = 0.2885 (derived), "d599" = 8.19502 (derived)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
node "Leader Text 23"
node "Cylindrical Surface 22"
node "Cylindrical Surface 23"
node "Feature Control Frame 68"
node "Feature Control Frame 70"
node "Datum Identifier 41" dims "d6" = 204.0382, "d231" = 9.14552 (derived), "d232" = 7.51656 (derived), "d233" = 0.508 (derived), "d234" = 0 (derived), "d235" = 0 (derived), "d236" = 1.524 (derived), "d237" = 0 (derived), "d238" = 0 (derived), "d247" = 27.94 (derived), "d315" = 5.33671 (derived), "d316" = 3.69003 (derived), "d347" = 15.24 (derived), "d348" = 0 (derived), "d349" = 0 (derived), "d505" = 0 (derived), "d506" = 0 (derived), "d541" = 3.50258 (derived), "d542" = 1.1618 (derived), "d543" = 1.524 (derived), "d544" = 0 (derived), "d545" = 0 (derived), "d598" = 0.2885 (derived), "d599" = 8.19502 (derived)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
node "Hole Note 2" dims "d5" = 291.1602, "d6" = 204.0382, "d141" = 22.86, "d142" = 22.86 (derived), "d143" = 22.86 (derived), "d144" = 22.86 (derived), "d145" = 22.86 (derived), "d146" = 22.86 (derived), "d147" = 22.86 (derived), "d148" = 22.86 (derived)
node "Feature Control Frame 71"
node "Datum Identifier 42" dims "d6" = 204.0382, "d231" = 9.14552 (derived), "d232" = 7.51656 (derived), "d233" = 0.508 (derived), "d234" = 0 (derived), "d235" = 0 (derived), "d236" = 1.524 (derived), "d237" = 0 (derived), "d238" = 0 (derived), "d247" = 27.94 (derived), "d315" = 5.33671 (derived), "d316" = 3.69003 (derived), "d347" = 15.24 (derived), "d348" = 0 (derived), "d349" = 0 (derived), "d505" = 0 (derived), "d506" = 0 (derived), "d541" = 3.50258 (derived), "d542" = 1.1618 (derived), "d543" = 1.524 (derived), "d544" = 0 (derived), "d545" = 0 (derived), "d598" = 0.2885 (derived), "d599" = 8.19502 (derived)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
node "Diameter Dimension 8" dims "d5" = 291.1602, "d6" = 204.0382, "d141" = 22.86, "d142" = 22.86 (derived), "d143" = 22.86 (derived), "d144" = 22.86 (derived), "d145" = 22.86 (derived), "d146" = 22.86 (derived), "d147" = 22.86 (derived), "d148" = 22.86 (derived), "d841" = 6.1468 (derived)
node "Feature Control Frame 75"
node "Datum Identifier 43" dims "d6" = 204.0382, "d231" = 9.14552 (derived), "d232" = 7.51656 (derived), "d233" = 0.508 (derived), "d234" = 0 (derived), "d235" = 0 (derived), "d236" = 1.524 (derived), "d237" = 0 (derived), "d238" = 0 (derived), "d247" = 27.94 (derived), "d315" = 5.33671 (derived), "d316" = 3.69003 (derived), "d347" = 15.24 (derived), "d348" = 0 (derived), "d349" = 0 (derived), "d505" = 0 (derived), "d506" = 0 (derived), "d541" = 3.50258 (derived), "d542" = 1.1618 (derived), "d543" = 1.524 (derived), "d544" = 0 (derived), "d545" = 0 (derived), "d598" = 0.2885 (derived), "d599" = 8.19502 (derived)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
node "Leader Text 24"
node "Diameter Dimension 2" dims "d5" = 291.1602, "d6" = 204.0382, "d141" = 22.86, "d142" = 22.86 (derived), "d143" = 22.86 (derived), "d144" = 22.86 (derived), "d145" = 22.86 (derived), "d146" = 22.86 (derived), "d147" = 22.86 (derived), "d148" = 22.86 (derived), "d848" = 5.4102 (derived)
node "Datum Identifier 44" dims "d6" = 204.0382, "d231" = 9.14552 (derived), "d232" = 7.51656 (derived), "d233" = 0.508 (derived), "d234" = 0 (derived), "d235" = 0 (derived), "d236" = 1.524 (derived), "d237" = 0 (derived), "d238" = 0 (derived), "d247" = 27.94 (derived), "d315" = 5.33671 (derived), "d316" = 3.69003 (derived), "d347" = 15.24 (derived), "d348" = 0 (derived), "d349" = 0 (derived), "d505" = 0 (derived), "d506" = 0 (derived), "d541" = 3.50258 (derived), "d542" = 1.1618 (derived), "d543" = 1.524 (derived), "d544" = 0 (derived), "d545" = 0 (derived), "d598" = 0.2885 (derived), "d599" = 8.19502 (derived)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
node "Diameter Dimension 1" dims "d5" = 291.1602, "d6" = 204.0382, "d141" = 22.86, "d142" = 22.86 (derived), "d143" = 22.86 (derived), "d144" = 22.86 (derived), "d145" = 22.86 (derived), "d146" = 22.86 (derived), "d147" = 22.86 (derived), "d148" = 22.86 (derived), "d852" = 5.4102 (derived)
node "Datum Identifier 45" dims "d6" = 204.0382, "d231" = 9.14552 (derived), "d232" = 7.51656 (derived), "d233" = 0.508 (derived), "d234" = 0 (derived), "d235" = 0 (derived), "d236" = 1.524 (derived), "d237" = 0 (derived), "d238" = 0 (derived), "d247" = 27.94 (derived), "d315" = 5.33671 (derived), "d316" = 3.69003 (derived), "d347" = 15.24 (derived), "d348" = 0 (derived), "d349" = 0 (derived), "d505" = 0 (derived), "d506" = 0 (derived), "d541" = 3.50258 (derived), "d542" = 1.1618 (derived), "d543" = 1.524 (derived), "d544" = 0 (derived), "d545" = 0 (derived), "d598" = 0.2885 (derived), "d599" = 8.19502 (derived)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
other parameters: "d10" = -3.429, "d35" = 47.8536, "d37" = 25.4, "d38" = 1.524, "d44" = 1.524 (= d38), "d45" = 1.524 (= d38), "d58" = 1.524 (= d38), "d59" = 1.524 (= d38), "d60" = 1.524 (= d38), "d61" = 25.4 (= d37), "d69" = 1.524, "d75" = 1.524, "d335" = 0, "d336" = 0, "d337" = 0, "d338" = 90 deg, "d339" = 0, "d340" = -90 deg, "d341" = 0, "d342" = -38.1, "d343" = 0, "d344" = -90 deg, "d345" = 0, "d346" = -90 deg, "d372" = 0, "d373" = 0, "d374" = -57.15, "d375" = -90 deg, "d376" = 0, "d377" = -90 deg, "d383" = 15.5702, "d384" = 0, "d385" = 0, "d386" = -90 deg, "d387" = 0, "d388" = -90 deg, "d394" = 0, "d395" = 0, "d396" = 0, "d397" = -90 deg, "d398" = 0, "d399" = -90 deg, "d400" = 0, "d401" = 0, "d402" = 0, "d403" = -90 deg, "d404" = 0, "d405" = -90 deg
